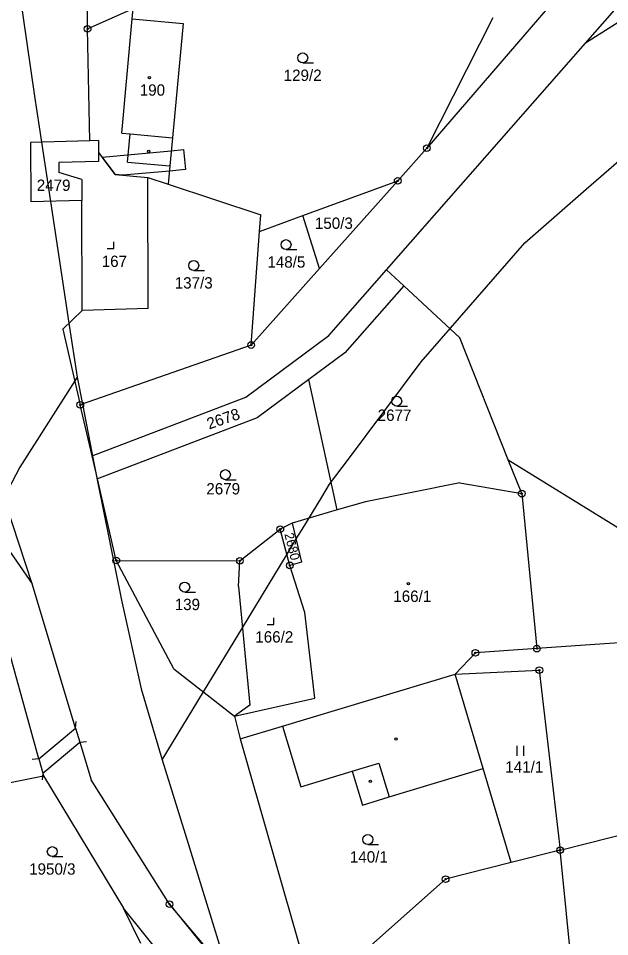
# Model space of a CAD drawing. Extents: x -546762 to -540209, y -1046851 to -1035694.
# Drawn here: x -542409.7 to -542321.1, y -1038576.7 to -1038439.2 of the extents above; entities that cross this region are included whole.
import ezdxf

# ---------------------------------------------------------------- set-up
doc = ezdxf.new("R2010")
doc.units = 0
for name, color, linetype in [('Vrstva 1', 7, 'Continuous'), ('Vrstva 18', 7, 'Continuous'), ('Vrstva 19', 7, 'Continuous'), ('Vrstva 24', 7, 'Continuous'), ('Vrstva 25', 7, 'Continuous'), ('Vrstva 26', 7, 'Continuous'), ('Vrstva 3', 7, 'Continuous'), ('Vrstva 30', 7, 'Continuous'), ('Vrstva 37', 7, 'Continuous'), ('Vrstva 4', 7, 'Continuous'), ('Vrstva 52', 7, 'Continuous'), ('Vrstva 6', 7, 'Continuous')]:
    doc.layers.add(name, color=color, linetype=linetype)

msp = doc.modelspace()

# ---------------------------------------------------------------- linework, layer by layer
at = {"layer": 'Vrstva 1'}
for p, q in [((-542398.98, -1038457.49), (-542399.3, -1038440.73)), ((-542386.39, -1038536.59), (-542395, -1038520.37)), ((-542366.76, -1038528.17), (-542368.99, -1038521.11)), ((-542376.44, -1038547.09), (-542365.39, -1038585.65))]:
    msp.add_line(p, q, dxfattribs=at)
for points in [[(-542324.68, -1038442.88), (-542295.36, -1038409.48)], [(-542318.14, -1038423.4), (-542348.44, -1038458.61)], [(-542399.3, -1038440.73), (-542399.24, -1038434.68)], [(-542312.81, -1038435.36), (-542324.68, -1038442.88)], [(-542399.3, -1038440.73), (-542392.45, -1038437.67)], [(-542392.6, -1038439.25), (-542392.45, -1038437.67)], [(-542392.6, -1038439.25), (-542384.98, -1038439.94)], [(-542384.98, -1038439.94), (-542386.57, -1038457.04)], [(-542338.54, -1038439.08), (-542348.44, -1038458.61)], [(-542354.48, -1038476.83), (-542324.68, -1038442.88)], [(-542398.98, -1038457.49), (-542407.84, -1038457.75)], [(-542407.84, -1038457.75), (-542407.81, -1038466.66)], [(-542397.67, -1038457.45), (-542398.98, -1038457.49)], [(-542397.67, -1038457.45), (-542397.66, -1038459.24)], [(-542386.57, -1038457.04), (-542386.96, -1038461.26)], [(-542397.66, -1038459.24), (-542397.66, -1038460.59)], [(-542397.66, -1038459.24), (-542395.17, -1038462.56)], [(-542348.44, -1038458.61), (-542352.82, -1038463.51)], [(-542397.66, -1038460.59), (-542403.63, -1038460.77)], [(-542403.63, -1038460.77), (-542403.62, -1038462.26)], [(-542400.18, -1038463.31), (-542403.62, -1038462.26)], [(-542386.96, -1038461.26), (-542387.22, -1038464.02)], [(-542400.18, -1038463.31), (-542400.17, -1038466.44)], [(-542395.17, -1038462.56), (-542390.27, -1038463.02)], [(-542390.21, -1038482.65), (-542390.27, -1038463.02)], [(-542390.27, -1038463.02), (-542387.22, -1038464.02)], [(-542367.06, -1038468.72), (-542352.82, -1038463.51)], [(-542352.82, -1038463.51), (-542364.53, -1038476.62)], [(-542387.22, -1038464.02), (-542373.34, -1038468.59)], [(-542400.17, -1038466.44), (-542407.81, -1038466.66)], [(-542400.12, -1038482.94), (-542400.17, -1038466.44)], [(-542373.52, -1038471.09), (-542373.34, -1038468.59)], [(-542373.52, -1038471.09), (-542367.06, -1038468.72)], [(-542364.53, -1038476.62), (-542367.06, -1038468.72)], [(-542374.78, -1038488.1), (-542373.52, -1038471.09)], [(-542364.53, -1038476.62), (-542374.78, -1038488.1)], [(-542363.13, -1038486.68), (-542354.48, -1038476.83)], [(-542354.48, -1038476.83), (-542351.91, -1038479.21)], [(-542351.91, -1038479.21), (-542360.75, -1038489.27)], [(-542343.5, -1038487.03), (-542351.91, -1038479.21)], [(-542390.21, -1038482.65), (-542400.12, -1038482.94)], [(-542400.12, -1038482.94), (-542403.01, -1038485.74)], [(-542403.01, -1038485.74), (-542400.39, -1038497.07)], [(-542375.59, -1038495.92), (-542363.13, -1038486.68)], [(-542336.24, -1038505.3), (-542343.5, -1038487.03)], [(-542374.78, -1038488.1), (-542400.39, -1038497.07)], [(-542360.75, -1038489.27), (-542366.13, -1038493.27)], [(-542366.13, -1038493.27), (-542373.89, -1038499.02)], [(-542361.87, -1038512.81), (-542366.13, -1038493.27)], [(-542398.62, -1038504.72), (-542375.59, -1038495.92)], [(-542407.62, -1038523.85), (-542416.38, -1038497.22)], [(-542398.62, -1038504.72), (-542400.39, -1038497.07)], [(-542373.89, -1038499.02), (-542397.82, -1038508.16)], [(-542397.82, -1038508.16), (-542398.62, -1038504.72)], [(-542336.24, -1038505.3), (-542314.9, -1038518.48)], [(-542334.23, -1038510.36), (-542336.24, -1038505.3)], [(-542395, -1038520.37), (-542397.82, -1038508.16)], [(-542343.5, -1038508.76), (-542357.65, -1038511.57)], [(-542343.5, -1038508.76), (-542334.23, -1038510.36)], [(-542334.23, -1038510.36), (-542331.96, -1038533.58)], [(-542357.65, -1038511.57), (-542361.87, -1038512.81)], [(-542361.87, -1038512.81), (-542368.64, -1038514.78)], [(-542376.48, -1038520.43), (-542370.42, -1038515.69)], [(-542368.64, -1038514.78), (-542370.42, -1038515.69)], [(-542368.99, -1038521.11), (-542370.42, -1038515.69)], [(-542368.64, -1038514.78), (-542367.23, -1038520.63)], [(-542395, -1038520.37), (-542376.48, -1038520.43)], [(-542376.68, -1038524.29), (-542376.48, -1038520.43)], [(-542367.23, -1038520.63), (-542368.99, -1038521.11)], [(-542401.09, -1038545.49), (-542407.62, -1038523.85)], [(-542376.68, -1038524.29), (-542375, -1038542.04)], [(-542406.6, -1038550.08), (-542413.1, -1038526.79)], [(-542365.26, -1038541), (-542366.76, -1038528.17)], [(-542300.72, -1038531.42), (-542331.96, -1038533.58)], [(-542331.96, -1038533.58), (-542341.18, -1038534.22)], [(-542341.18, -1038534.22), (-542344.23, -1038537.42)], [(-542386.39, -1038536.59), (-542377.28, -1038543.71)], [(-542344.23, -1038537.42), (-542331.59, -1038536.81)], [(-542340, -1038551.56), (-542344.23, -1038537.42)], [(-542331.59, -1038536.81), (-542328.48, -1038563.76)], [(-542377.28, -1038543.71), (-542365.26, -1038541)], [(-542375, -1038542.04), (-542377.28, -1038543.71)], [(-542377.28, -1038543.71), (-542376.44, -1038547.09)], [(-542401.09, -1038545.49), (-542400.46, -1038547.59)], [(-542376.44, -1038547.09), (-542370.1, -1038545.19)], [(-542370.1, -1038545.19), (-542367.36, -1038554.26)], [(-542400.46, -1038547.59), (-542398.76, -1038553.23)], [(-542406.6, -1038550.08), (-542406.01, -1038552.21)], [(-542354.1, -1038555.8), (-542340, -1038551.56)], [(-542335.79, -1038565.61), (-542340, -1038551.56)], [(-542413.18, -1038554.09), (-542405.89, -1038552.63)], [(-542406.01, -1038552.21), (-542405.89, -1038552.63)], [(-542405.89, -1038552.63), (-542393.93, -1038572.44)], [(-542367.36, -1038554.26), (-542359.64, -1038551.94)], [(-542359.64, -1038551.94), (-542358.1, -1038557.03)], [(-542387.02, -1038571.86), (-542398.76, -1038553.23)], [(-542358.1, -1038557.03), (-542354.1, -1038555.8)], [(-542328.48, -1038563.76), (-542298.08, -1038556.07)], [(-542328.48, -1038563.76), (-542335.79, -1038565.61)], [(-542325.63, -1038592.39), (-542328.48, -1038563.76)], [(-542335.79, -1038565.61), (-542345.63, -1038568.11)], [(-542345.63, -1038568.11), (-542365.39, -1038585.65)], [(-542387.02, -1038571.86), (-542369.2, -1038593.88)], [(-542368.48, -1038593.81), (-542387.02, -1038571.86)], [(-542391.32, -1038577.75), (-542393.93, -1038572.44)], [(-542375.04, -1038595.99), (-542393.93, -1038572.44)]]:
    msp.add_lwpolyline(points, dxfattribs=at)
at = {"layer": 'Vrstva 24'}
for centre, radius in [((-542399.3, -1038440.73), 0.5), ((-542399.3, -1038440.73), 0.1), ((-542348.44, -1038458.61), 0.5), ((-542348.44, -1038458.61), 0.1), ((-542352.82, -1038463.51), 0.5), ((-542352.82, -1038463.51), 0.1), ((-542374.78, -1038488.1), 0.5), ((-542374.78, -1038488.1), 0.1), ((-542400.39, -1038497.07), 0.5), ((-542400.39, -1038497.07), 0.1), ((-542334.23, -1038510.36), 0.5), ((-542334.23, -1038510.36), 0.1), ((-542370.42, -1038515.69), 0.5), ((-542370.42, -1038515.69), 0.1), ((-542395, -1038520.37), 0.5), ((-542376.48, -1038520.43), 0.5), ((-542395, -1038520.37), 0.1), ((-542376.48, -1038520.43), 0.1), ((-542368.99, -1038521.11), 0.5), ((-542368.99, -1038521.11), 0.1), ((-542341.18, -1038534.22), 0.5), ((-542331.96, -1038533.58), 0.5), ((-542331.96, -1038533.58), 0.1), ((-542341.18, -1038534.22), 0.1), ((-542331.59, -1038536.81), 0.5), ((-542331.59, -1038536.81), 0.1), ((-542328.48, -1038563.76), 0.5), ((-542328.48, -1038563.76), 0.1), ((-542345.63, -1038568.11), 0.5), ((-542345.63, -1038568.11), 0.1), ((-542387.02, -1038571.86), 0.5), ((-542387.02, -1038571.86), 0.1)]:
    msp.add_circle(centre, radius, dxfattribs=at)
at = {"layer": 'Vrstva 25'}
for p, q in [((-542367.06, -1038445.84), (-542365.46, -1038445.84)), ((-542369.56, -1038473.81), (-542367.96, -1038473.81)), ((-542383.4, -1038476.94), (-542381.8, -1038476.94)), ((-542352.97, -1038497.25), (-542351.37, -1038497.25)), ((-542378.65, -1038508.27), (-542377.05, -1038508.27)), ((-542384.75, -1038525.11), (-542383.15, -1038525.11)), ((-542334.89, -1038549.62), (-542334.89, -1038548.12)), ((-542333.89, -1038549.62), (-542333.89, -1038548.12)), ((-542357.29, -1038562.93), (-542355.69, -1038562.93)), ((-542404.59, -1038564.74), (-542402.99, -1038564.74))]:
    msp.add_line(p, q, dxfattribs=at)
for points in [[(-542396.35, -1038473.64), (-542395.35, -1038473.64), (-542395.35, -1038472.64)], [(-542372.37, -1038529.97), (-542371.37, -1038529.97), (-542371.37, -1038528.97)]]:
    msp.add_lwpolyline(points, dxfattribs=at)
for centre, radius in [((-542367.06, -1038445.09), 0.75), ((-542390.04, -1038448.05), 0.175), ((-542390.13, -1038459.07), 0.175), ((-542369.56, -1038473.06), 0.75), ((-542383.4, -1038476.19), 0.75), ((-542352.97, -1038496.5), 0.75), ((-542378.65, -1038507.52), 0.75), ((-542384.75, -1038524.36), 0.75), ((-542351.22, -1038523.87), 0.175), ((-542353.08, -1038547.13), 0.175), ((-542356.9, -1038553.47), 0.175), ((-542357.29, -1038562.18), 0.75), ((-542404.59, -1038563.99), 0.75)]:
    msp.add_circle(centre, radius, dxfattribs=at)
at = {"layer": 'Vrstva 26'}
for p, q in [((-542401.09, -1038545.49), (-542401, -1038544.49)), ((-542400.46, -1038547.59), (-542399.46, -1038547.5)), ((-542406.6, -1038550.08), (-542407.6, -1038550.17)), ((-542406.01, -1038552.21), (-542406.1, -1038553.21))]:
    msp.add_line(p, q, dxfattribs=at)
at = {"layer": 'Vrstva 3'}
for points in [[(-542394.19, -1038456.35), (-542392.6, -1038439.25)], [(-542392.6, -1038439.25), (-542384.98, -1038439.94)], [(-542384.98, -1038439.94), (-542386.57, -1038457.04)], [(-542394.19, -1038456.35), (-542392.94, -1038456.46)], [(-542392.94, -1038456.46), (-542386.57, -1038457.04)], [(-542343.5, -1038508.76), (-542357.65, -1038511.57)], [(-542343.5, -1038508.76), (-542334.23, -1038510.36)], [(-542334.23, -1038510.36), (-542331.96, -1038533.58)], [(-542357.65, -1038511.57), (-542361.87, -1038512.81)], [(-542361.87, -1038512.81), (-542368.64, -1038514.78)], [(-542368.64, -1038514.78), (-542367.23, -1038520.63)], [(-542367.23, -1038520.63), (-542368.99, -1038521.11)], [(-542366.76, -1038528.17), (-542368.99, -1038521.11)], [(-542365.26, -1038541), (-542366.76, -1038528.17)], [(-542331.96, -1038533.58), (-542341.18, -1038534.22)], [(-542341.18, -1038534.22), (-542344.23, -1038537.42)], [(-542370.1, -1038545.19), (-542344.23, -1038537.42)], [(-542377.28, -1038543.71), (-542365.26, -1038541)], [(-542377.28, -1038543.71), (-542376.44, -1038547.09)], [(-542376.44, -1038547.09), (-542370.1, -1038545.19)]]:
    msp.add_lwpolyline(points, dxfattribs=at)
at = {"layer": 'Vrstva 30'}
msp.add_lwpolyline([(-542386.75, -1038459), (-542384.91, -1038458.83), (-542384.64, -1038461.82), (-542387.03, -1038462.04), (-542394, -1038462.67), (-542395.17, -1038462.56), (-542397.13, -1038459.94), (-542386.75, -1038459)], dxfattribs=at)
at = {"layer": 'Vrstva 37'}
for centre in [(-542390.04, -1038448.05), (-542351.22, -1038523.87)]:
    msp.add_circle(centre, 0.175, dxfattribs=at)
at = {"layer": 'Vrstva 4'}
for points in [[(-542394.19, -1038456.35), (-542392.6, -1038439.25)], [(-542394.19, -1038456.35), (-542392.94, -1038456.46)], [(-542393.33, -1038460.69), (-542392.94, -1038456.46)], [(-542392.94, -1038456.46), (-542386.57, -1038457.04)], [(-542393.33, -1038460.69), (-542386.96, -1038461.26)], [(-542370.1, -1038545.19), (-542344.23, -1038537.42)], [(-542406.6, -1038550.08), (-542401.09, -1038545.49)], [(-542406.01, -1038552.21), (-542400.46, -1038547.59)], [(-542359.64, -1038551.94), (-542355.63, -1038550.73)], [(-542355.63, -1038550.73), (-542354.1, -1038555.8)]]:
    msp.add_lwpolyline(points, dxfattribs=at)
at = {"layer": 'Vrstva 52'}
for points in [[(-542431.52, -1038326.72), (-542418.7, -1038378.03), (-542414, -1038405.08), (-542413.21, -1038409.61), (-542412.49, -1038414.59), (-542411.78, -1038419.51), (-542410.16, -1038430.73), (-542407.26, -1038450.8), (-542406.21, -1038457.7), (-542404.86, -1038466.58), (-542402.09, -1038484.84), (-542400.86, -1038492.91)], [(-542388.11, -1038550.23), (-542381.94, -1038540.07), (-542376.1, -1038530.45), (-542369.39, -1038519.41), (-542367.78, -1038516.75), (-542367.15, -1038515.71), (-542364.21, -1038510.88), (-542363.03, -1038508.94), (-542360.21, -1038505.18), (-542349.31, -1038490.64), (-542333.76, -1038472.79), (-542324.58, -1038464.77), (-542319.68, -1038460.49), (-542315.43, -1038456.78), (-542306.99, -1038450.12), (-542301.83, -1038446.06), (-542285.89, -1038434.29), (-542272.56, -1038425.4)], [(-542400.86, -1038492.91), (-542401.22, -1038493.48), (-542409.48, -1038506.4), (-542411.84, -1038511.01), (-542413.84, -1038514.89), (-542414.45, -1038516.08), (-542416.51, -1038521.97), (-542416.6, -1038522.22), (-542418.11, -1038526.54), (-542420.2, -1038536.48), (-542421.59, -1038546.58), (-542422.03, -1038549.82), (-542422.27, -1038555.69), (-542422.81, -1038568.65), (-542422.58, -1038575.48), (-542422.39, -1038581.2)], [(-542400.86, -1038492.91), (-542400.07, -1038496.96), (-542398.67, -1038504.18), (-542398.56, -1038504.73), (-542398.26, -1038506.27), (-542397.82, -1038508.53), (-542394.24, -1038526.32), (-542391.25, -1038539.62), (-542388.11, -1038550.23)], [(-542388.11, -1038550.23), (-542384.23, -1038562.78), (-542378.4, -1038581.76), (-542378.31, -1038582.17), (-542378.17, -1038582.79), (-542376.42, -1038590.84), (-542375.97, -1038594.83), (-542375.07, -1038602.8), (-542374.47, -1038612.96), (-542374.32, -1038627.16), (-542374.34, -1038627.5), (-542374.77, -1038635.83), (-542375.38, -1038641.03), (-542375.71, -1038643.82), (-542375.97, -1038645.99), (-542378.51, -1038661.68), (-542381.34, -1038674.09), (-542385.09, -1038689.61), (-542387.78, -1038701.12), (-542389.12, -1038709.64)]]:
    msp.add_lwpolyline(points, dxfattribs=at)
at = {"layer": 'Vrstva 6'}
msp.add_lwpolyline([(-542423.08, -1038501.56), (-542407.62, -1038523.85)], dxfattribs=at)

# ---------------------------------------------------------------- texts
at = {"layer": 'Vrstva 18'}
for s, p in [('129/2', (-542369.91, -1038448.54)), ('2479', (-542406.92, -1038465.01)), ('150/3', (-542365.23, -1038470.7)), ('148/5', (-542372.35, -1038476.51)), ('137/3', (-542386.24, -1038479.64)), ('2677', (-542355.82, -1038499.46)), ('2679', (-542381.5, -1038510.48)), ('139', (-542386.24, -1038527.81)), ('141/1', (-542336.69, -1038552.15)), ('140/1', (-542359.99, -1038565.63)), ('1950/3', (-542408.06, -1038567.44))]:
    msp.add_text(s, height=1.7, dxfattribs=at).set_placement(p)
for s, height, rotation, p in [('2678', 1.7, 18.8397, (-542381.09, -1038500.76)), ('2680', 1.4, 284.0152, (-542369.82, -1038516.42))]:
    msp.add_text(s, height=height, rotation=rotation, dxfattribs=at).set_placement(p)
at = {"layer": 'Vrstva 19'}
for s, p in [('190', (-542391.48, -1038450.75)), ('167', (-542397.18, -1038476.41)), ('166/1', (-542353.48, -1038526.58)), ('166/2', (-542374.16, -1038532.67))]:
    msp.add_text(s, height=1.7, dxfattribs=at).set_placement(p)

doc.saveas('drawing.dxf')
